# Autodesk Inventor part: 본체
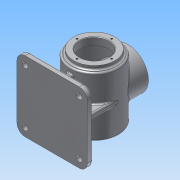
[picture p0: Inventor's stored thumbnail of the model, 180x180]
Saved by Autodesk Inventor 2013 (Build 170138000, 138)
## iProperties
Created: 2015-07
Part Number: 본체
Material: 알루미늄 6061
Document SubType Name: Modeling
Designer: Administrator
Density: 2.71 g/cm^3
Mass: 1277.74 g
Surface Area: 1267.61 cm^2
Volume: 471.49 cm^3
Author: Administrator
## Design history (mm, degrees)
sketch "스케치1"
  geometry: C1 r 45 at (0, 0); 1 further point
  constraints: 1 centre point, 1 coincident
  dimensions: "d0" = 90 diameter of C1
extrude "돌출1" new body sketch "스케치1" stored distance "d1" = 110; taper "d2" = 0 deg
node "작업 평면1"
sketch "스케치2"
  geometry: C1 r 38 at (0, 0); 1 further point
  constraints: 1 centre point, 1 coincident
  dimensions: "d4" = 76 diameter of C1
extrude "돌출2" join sketch "스케치2" stored distance "d5" = 110; taper "d6" = 0 deg
node "작업 평면2"
sketch "스케치3"
  geometry: L1 (65, -65)-(-65, -65); L2 (-65, -65)-(-65, 65); L3 (-65, 65)-(65, 65); L4 (65, 65)-(65, -65); L5 (65, -65)-(-65, 65); L6 (-65, -65)-(65, 65); 1 further point
  constraints: 12 end point, 2 midpoint, 2 parallel, 1 horizontal, 1 perpendicular
  dimensions: "d8" = 130 distance of L1.end L2.end; "d10" = 130 distance of L2.end L3.end
extrude "돌출3" join sketch "스케치3" distance "d11" = 10; taper "d12" = 0 deg
sketch "스케치4"
  geometry: C1 r 45 at (0, 0) reference; C2 r 38 at (0, 0)
  constraints: 1 centre point, 1 coincident
  dimensions: "d13" = 76 diameter of C2
extrude "돌출4" join sketch "스케치4" distance "d14" = 7; taper "d15" = 0 deg
node "작업 평면3"
sketch "스케치5"
  geometry: C1 r 40 at (0, 0); 1 further point
  constraints: 1 centre point, 1 coincident
  dimensions: "d17" = 80 diameter of C1
extrude "돌출5" cut sketch "스케치5" distance "d18" = 96; taper "d19" = 0 deg
hole "구멍1" diameter "d22" = 54; stored, may be unused: countersink angle "d26" = 90 deg, drill point angle "d28" = 0 deg; dims "d20" = 10, "d21" = 10, "d23" = 6, "d24" = 4, "d25" = 2, "d27" = 14
hole "구멍2" diameter "d31" = 54; stored, may be unused: countersink angle "d35" = 90 deg, drill point angle "d37" = 0 deg; dims "d29" = 10, "d30" = 10, "d32" = 6, "d33" = 4, "d34" = 2, "d36" = 14
sketch "스케치6"
  geometry: C1 r 27 at (0, 0) reference; 1 further point
  constraints: 1 vertical alignment
  dimensions: "d38" = 32 distance of point (0, 32) C1.centre
hole "구멍3" sketch "스케치6" at (0, 32) diameter "d39" = 3.242; stored, may be unused: countersink angle "d43" = 90 deg, drill point angle "d45" = 118 deg; dims "d40" = 8, "d41" = 4, "d42" = 2, "d44" = 10
sketch "스케치7"
  geometry: C1 r 27 at (0, 0) reference; 1 further point
  constraints: 1 vertical alignment
  dimensions: "d49" = 32 distance of C1.centre point (0, 32)
hole "구멍4" sketch "스케치7" at (0, 32) diameter "d50" = 3.242; stored, may be unused: countersink angle "d54" = 90 deg, drill point angle "d56" = 118 deg; dims "d51" = 8, "d52" = 4, "d53" = 2, "d55" = 10
sketch "스케치8"
  geometry: L1 (-5, 45)-(5, 45); L2 (5, 45)-(5, -45); L3 (5, -45)-(-5, -45); L4 (-5, -45)-(-5, 45); L5 (-5, 45)-(5, -45); L6 (5, 45)-(-5, -45); L7 (-45, 5)-(45, 5); L8 (45, 5)-(45, -5); L9 (45, -5)-(-45, -5); L10 (-45, -5)-(-45, 5); L11 (-45, 5)-(45, -5); L12 (45, 5)-(-45, -5); 2 further points
  constraints: 24 end point, 4 midpoint, 4 parallel, 2 horizontal, 2 perpendicular, 1 coincident
  dimensions: "d62" = 90 distance of L1.end L2.end; "d64" = 90 distance of L7.start L7.end; "d65" = 10 distance between parallel lines of L4 L2; "d66" = 10 distance between parallel lines of L9 L7
extrude "돌출6" join sketch "스케치8" stored distance "d67" = 96; taper "d68" = 0 deg
sketch "스케치9"
  geometry: C1 r 7.5 at (50, -50); 1 further point
  constraints: 1 centre point
  dimensions: "d69" = 15 diameter of C1; "d71" = 50 horizontal distance of C1.centre point (0, 0); "d72" = 50 horizontal distance of point (0, 0) C1.centre
extrude "돌출7" join sketch "스케치9" distance "d73" = 3; taper "d74" = 0 deg
hole "구멍5" diameter "d77" = 10; stored, may be unused: countersink angle "d81" = 90 deg, drill point angle "d83" = 118 deg; dims "d75" = 10, "d76" = 10, "d78" = 8, "d79" = 4, "d80" = 2, "d82" = 10
fillet "모깎기1" dims "d87" = 3, "d88" = 15
fillet "모깎기2" dims "d89" = 3
chamfer "모따기1" distance "d90" = 1; stored, may be unused: second distance "d91" = 2, angle "d92" = 45 deg
sketch "스케치10"
  geometry: C1 r 42 at (0, 0) reference; 1 further point
  constraints: 1 coincident, 1 other
feature "엠보싱1" sketch "스케치10" dims "d13" = 76, "d93" = 0.5, "d94" = 0
node "솔리드1"
pattern_circular "원형 패턴1" dims angle "d47" = 360 deg
pattern_circular "원형 패턴2" dims angle "d58" = 360 deg
pattern_circular "원형 패턴3" dims angle "d85" = 360 deg
other parameters: "d3" = 62, "d7" = -78, "d16" = -7
